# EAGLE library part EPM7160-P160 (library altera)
EPM7160S MAX 7000 family
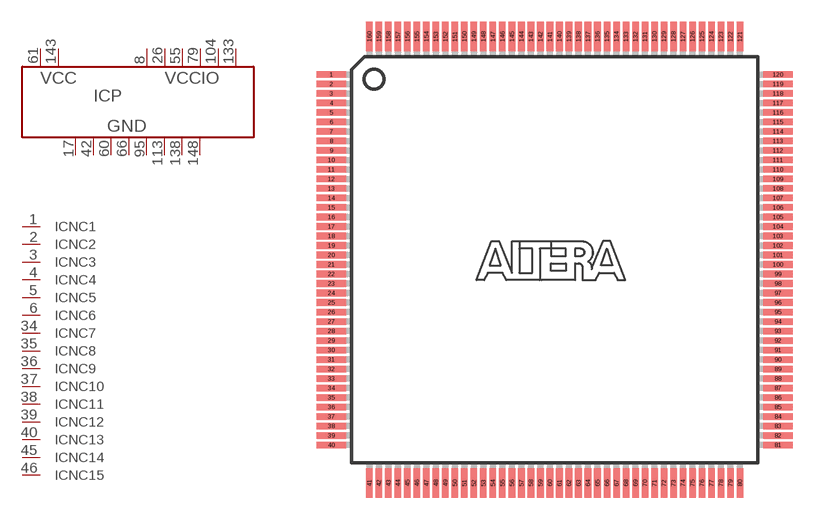
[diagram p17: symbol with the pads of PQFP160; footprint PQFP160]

Designator prefix IC; gates P=PWR8-2-6 NC1=NC NC2=NC NC3=NC NC4=NC NC5=NC NC6=NC NC7=NC NC8=NC NC9=NC NC10=NC NC11=NC NC12=NC NC13=NC NC14=NC NC15=NC NC16=NC NC17=NC NC18=NC NC19=NC NC20=NC NC21=NC NC22=NC NC23=NC NC24=NC NC25=NC NC26=NC NC27=NC NC28=NC NC29=NC NC30=NC NC31=NC NC32=NC NC33=NC NC34=NC NC35=NC NC36=NC NC37=NC NC38=NC NC39=NC NC40=NC _=7160P160

## EPM7160-P160 (MPN: EPM7160SQC160-10N; OC_FARNELL: 1549437; OC_NEWARK: 51R9800)  [PQFP160]
1  NC1:NC  nc
2  NC2:NC  nc
3  NC3:NC  nc
4  NC4:NC  nc
5  NC5:NC  nc
6  NC6:NC  nc
7  _:IO29
8  P:VCCIO  pwr
9  _:IO27
10  _:IO25
11  _:IO24
12  _:IO22
13  _:IO21
14  _:IO19
15  _:IO17
16  _:IO41
17  P:GND  pwr
18  _:IO43
19  _:IO45
20  _:IO46
21  _:IO48
22  _:IO40
23  _:IO38
24  _:IO37
25  _:IO35
26  P:VCCIO  pwr
27  _:IO33
28  _:IO64
29  _:IO62
30  _:IO61
31  _:IO59
32  _:IO57
33  _:IO56
34  NC7:NC  nc
35  NC8:NC  nc
36  NC9:NC  nc
37  NC10:NC  nc
38  NC11:NC  nc
39  NC12:NC  nc
40  NC13:NC  nc
41  _:IO54
42  P:GND  pwr
43  _:IO53
44  _:IO51
45  NC14:NC  nc
46  NC15:NC  nc
47  NC16:NC  nc
48  _:IO49
49  _:IO80
50  _:IO78
51  _:IO77-TDI
52  _:IO75
53  _:IO73
54  _:IO72
55  P:VCCIO  pwr
56  _:IO70
57  _:IO69
58  _:IO67
59  _:IO65
60  P:GND  pwr
61  P:VCC  pwr
62  _:IO81
63  _:IO83
64  _:IO85
65  _:IO86
66  P:GND  pwr
67  _:IO88
68  _:IO89
69  _:IO91
70  _:IO93
71  _:IO94
72  _:IO96
73  _:IO97
74  NC17:NC  nc
75  NC18:NC  nc
76  NC19:NC  nc
77  _:IO99
78  _:IO101
79  P:VCCIO  pwr
80  _:IO102
81  NC20:NC  nc
82  NC21:NC  nc
83  NC22:NC  nc
84  NC23:NC  nc
85  NC24:NC  nc
86  NC25:NC  nc
87  NC26:NC  nc
88  _:IO104
89  _:IO105
90  _:IO107
91  _:IO109-TMS
92  _:IO110
93  _:IO112
94  _:IO113
95  P:GND  pwr
96  _:IO115
97  _:IO117
98  _:IO118
99  _:IO120
100  _:IO128
101  _:IO126
102  _:IO125
103  _:IO123
104  P:VCCIO  pwr
105  _:IO121
106  _:IO129
107  _:IO131
108  _:IO133
109  _:IO134
110  _:IO136
111  _:IO137
112  _:IO139
113  P:GND  pwr
114  _:TDO-IO141
115  NC27:NC  nc
116  NC28:NC  nc
117  NC29:NC  nc
118  NC30:NC  nc
119  NC31:NC  nc
120  NC32:NC  nc
121  _:IO142
122  _:IO144
123  _:IO145
124  NC33:NC  nc
125  NC34:NC  nc
126  NC35:NC  nc
127  NC36:NC  nc
128  _:IO147
129  _:IO149
130  _:IO150
131  _:IO152
132  _:IO153
133  P:VCCIO  pwr
134  _:IO155
135  _:IO157
136  _:IO158
137  _:IO160
138  P:GND  pwr
139  _:GCLK1  in
140  _:OE1  in
141  _:GCLR/  in
142  _:OE2-GCLK2  in
143  P:VCC  pwr
144  _:IO16
145  _:IO14
146  _:IO13
147  _:IO11
148  P:GND  pwr
149  _:IO9
150  _:IO8
151  _:IO6
152  _:IO5
153  _:IO3
154  NC37:NC  nc
155  NC38:NC  nc
156  NC39:NC  nc
157  NC40:NC  nc
158  _:IO1
159  _:IO32
160  _:IO30

## Footprint PQFP160 (pad centres in mm)
Plastic Quad Flat Pack
smd 2 x 0.45: 1 -15.275,12.675; 2 -15.275,12.025; 3 -15.275,11.375; 4 -15.275,10.725; 5 -15.275,10.075; 6 -15.275,9.425; 7 -15.275,8.775; 8 -15.275,8.125; 9 -15.275,7.475; 10 -15.275,6.825; 11 -15.275,6.175; 12 -15.275,5.525; 13 -15.275,4.875; 14 -15.275,4.225; 15 -15.275,3.575; 16 -15.275,2.925; 17 -15.275,2.275; 18 -15.275,1.625; 19 -15.275,0.975; 20 -15.275,0.325; 21 -15.275,-0.325; 22 -15.275,-0.975; 23 -15.275,-1.625; 24 -15.275,-2.275; 25 -15.275,-2.925; 26 -15.275,-3.575; 27 -15.275,-4.225; 28 -15.275,-4.875; 29 -15.275,-5.525; 30 -15.275,-6.175; 31 -15.275,-6.825; 32 -15.275,-7.475; 33 -15.275,-8.125; 34 -15.275,-8.775; 35 -15.275,-9.425; 36 -15.275,-10.075; 37 -15.275,-10.725; 38 -15.275,-11.375; 39 -15.275,-12.025; 40 -15.275,-12.675; 81 15.275,-12.675; 82 15.275,-12.025; 83 15.275,-11.375; 84 15.275,-10.725; 85 15.275,-10.075; 86 15.275,-9.425; 87 15.275,-8.775; 88 15.275,-8.125; 89 15.275,-7.475; 90 15.275,-6.825; 91 15.275,-6.175; 92 15.275,-5.525; 93 15.275,-4.875; 94 15.275,-4.225; 95 15.275,-3.575; 96 15.275,-2.925; 97 15.275,-2.275; 98 15.275,-1.625; 99 15.275,-0.975; 100 15.275,-0.325; 101 15.275,0.325; 102 15.275,0.975; 103 15.275,1.625; 104 15.275,2.275; 105 15.275,2.925; 106 15.275,3.575; 107 15.275,4.225; 108 15.275,4.875; 109 15.275,5.525; 110 15.275,6.175; 111 15.275,6.825; 112 15.275,7.475; 113 15.275,8.125; 114 15.275,8.775; 115 15.275,9.425; 116 15.275,10.075; 117 15.275,10.725; 118 15.275,11.375; 119 15.275,12.025; 120 15.275,12.675
smd 0.45 x 2: 41 -12.675,-15.275; 42 -12.025,-15.275; 43 -11.375,-15.275; 44 -10.725,-15.275; 45 -10.075,-15.275; 46 -9.425,-15.275; 47 -8.775,-15.275; 48 -8.125,-15.275; 49 -7.475,-15.275; 50 -6.825,-15.275; 51 -6.175,-15.275; 52 -5.525,-15.275; 53 -4.875,-15.275; 54 -4.225,-15.275; 55 -3.575,-15.275; 56 -2.925,-15.275; 57 -2.275,-15.275; 58 -1.625,-15.275; 59 -0.975,-15.275; 60 -0.325,-15.275; 61 0.325,-15.275; 62 0.975,-15.275; 63 1.625,-15.275; 64 2.275,-15.275; 65 2.925,-15.275; 66 3.575,-15.275; 67 4.225,-15.275; 68 4.875,-15.275; 69 5.525,-15.275; 70 6.175,-15.275; 71 6.825,-15.275; 72 7.475,-15.275; 73 8.125,-15.275; 74 8.775,-15.275; 75 9.425,-15.275; 76 10.075,-15.275; 77 10.725,-15.275; 78 11.375,-15.275; 79 12.025,-15.275; 80 12.675,-15.275; 121 12.675,15.275; 122 12.025,15.275; 123 11.375,15.275; 124 10.725,15.275; 125 10.075,15.275; 126 9.425,15.275; 127 8.775,15.275; 128 8.125,15.275; 129 7.475,15.275; 130 6.825,15.275; 131 6.175,15.275; 132 5.525,15.275; 133 4.875,15.275; 134 4.225,15.275; 135 3.575,15.275; 136 2.925,15.275; 137 2.275,15.275; 138 1.625,15.275; 139 0.975,15.275; 140 0.325,15.275; 141 -0.325,15.275; 142 -0.975,15.275; 143 -1.625,15.275; 144 -2.275,15.275; 145 -2.925,15.275; 146 -3.575,15.275; 147 -4.225,15.275; 148 -4.875,15.275; 149 -5.525,15.275; 150 -6.175,15.275; 151 -6.825,15.275; 152 -7.475,15.275; 153 -8.125,15.275; 154 -8.775,15.275; 155 -9.425,15.275; 156 -10.075,15.275; 157 -10.725,15.275; 158 -11.375,15.275; 159 -12.025,15.275; 160 -12.675,15.275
